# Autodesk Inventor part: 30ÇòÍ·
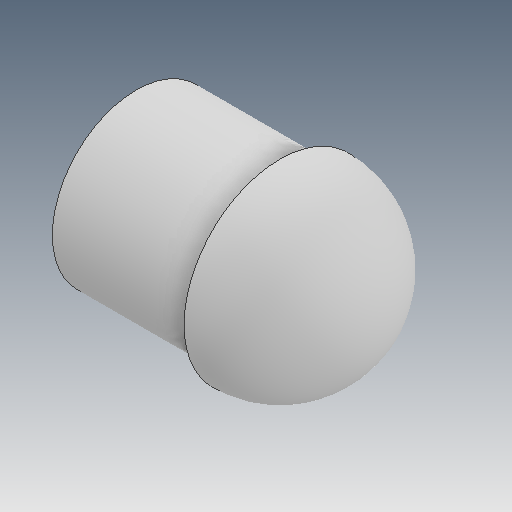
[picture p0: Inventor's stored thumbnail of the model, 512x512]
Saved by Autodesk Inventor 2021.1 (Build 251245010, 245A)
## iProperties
Created: 2019-12
Part Number: 30ÇòÍ·
Material: Ogólny
Document SubType Name: Modeling
Designer: user
Density: 1 g/cm^3
Appearance: Domyślna
Author: user
Revision Number: ÈÎºÎ
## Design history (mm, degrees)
feature "ÊäÈë1"
node "Bryła1"
